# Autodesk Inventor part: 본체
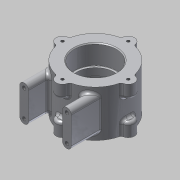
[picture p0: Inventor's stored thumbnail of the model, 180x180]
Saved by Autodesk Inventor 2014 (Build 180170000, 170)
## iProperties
Created: 2015-03
Part Number: 본체
Material: 알루미늄 6061
Document SubType Name: Modeling
Designer: MYHOME
Mass: 450.776 g
Surface Area: 332.745 cm^2
Volume: 166.338 cm^3
Density: 2.71 g/cm^3
Appearance: 알루미늄 - 평지
Author: MYHOME
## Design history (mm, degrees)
sketch "스케치1"
  geometry: C1 r 37 at (0, 0); 1 further point
  constraints: 1 centre point, 1 coincident
  dimensions: "d0" = 74 diameter of C1
extrude "돌출1" new body sketch "스케치1" stored distance "d1" = 52; taper "d2" = 0 deg
sketch "스케치2"
  geometry: C1 r 7 at (0, 37); 1 further point
  constraints: 2 vertical alignment, 1 centre point, 1 other
  dimensions: "d3" = 7 radius of C1
extrude "돌출2" join sketch "스케치2" distance "d4" = 15; taper "d5" = 0 deg
hole "구멍1" diameter "d11" = 42; stored, may be unused: countersink angle "d15" = 90 deg, drill point angle "d17" = 0 deg; dims "d9" = 10, "d10" = 10, "d12" = 6, "d13" = 47, "d14" = 22, "d16" = 26
sketch "스케치3"
  geometry: L1 (-29, -22.978)-(-19, -22.978); L2 (-19, -22.978)-(-19, -56); L3 (-19, -56)-(-29, -56); L4 (-29, -56)-(-29, -22.978); L5 (-29, -22.978)-(-19, -56); L6 (-19, -22.978)-(-29, -56); L7 (19, -22.978)-(29, -22.978); L8 (29, -22.978)-(29, -56); L9 (29, -56)-(19, -56); L10 (19, -56)-(19, -22.978); L11 (19, -22.978)-(29, -56); L12 (29, -22.978)-(19, -56); A1 r 37 centre (0, 0) between (-36.338, -6.969) and (-6.969, -36.338) reference; A2 r 37 centre (0, 0) between (6.969, -36.338) and (36.338, -6.969) reference; 3 further points
  constraints: 24 end point, 4 midpoint, 4 parallel, 2 horizontal, 2 perpendicular, 2 point on circle, 1 collinear
  dimensions: "d18" = 48 distance of point (24, -39.489) point (-24, -39.489); "d19" = 24 horizontal distance of point (-24, -39.489) point (0, 0); "d20" = 56 distance from line of L3 point (0, 0); "d21" = 10 distance of L1.start L1.end; "d22" = 10 distance of L7.start L7.end
extrude "돌출3" join sketch "스케치3" stored distance "d23" = 40; taper "d24" = 0 deg
sketch "스케치4"
  geometry: A1 r 7 centre (0, 37) between (6.969, 36.338) and (-6.969, 36.338) reference; A2 r 7 centre (-37, 0) between (-36.338, 6.969) and (-36.338, -6.969) reference; A3 r 7 centre (0, -37) between (-6.969, -36.338) and (6.969, -36.338) reference; A4 r 7 centre (37, 0) between (36.338, -6.969) and (36.338, 6.969) reference; 4 further points
  constraints: 4 coincident
hole "구멍2" sketch "스케치4" at (0, 37), (-37, 0), (0, -37), (37, 0) diameter "d25" = 3.242; stored, may be unused: countersink angle "d29" = 90 deg, drill point angle "d31" = 118 deg; dims "d26" = 8, "d27" = 47, "d28" = 22, "d30" = 11
chamfer "모따기1" distance "d32" = 1; stored, may be unused: second distance "d33" = 2, angle "d34" = 45 deg
fillet "모깎기1" dims "d35" = 3
fillet "모깎기2" dims "d36" = 0.3
fillet "모깎기3" dims "d37" = 5
fillet "모깎기4" dims "d38" = 3
fillet "모깎기5" dims "d39" = 3
sketch "스케치5"
  geometry: L1 (43, 30)-(43, 0) reference; L2 (53, 30)-(53, 0) reference; A1 r 5 centre (0, 0) between (-5, 0) and (5, 0) reference; A2 r 5 centre (0, 30) between (5, 30) and (-5, 30) reference; A3 r 5 centre (48, 30) between (53, 30) and (43, 30) reference; A4 r 5 centre (48, 0) between (43, 0) and (53, 0) reference; 5 further points
  constraints: 4 coincident
hole "구멍3" sketch "스케치5" at (0, 30), (0, 0), (48, 0), (48, 30) diameter "d40" = 4.134; stored, may be unused: countersink angle "d44" = 90 deg, drill point angle "d46" = 118 deg; dims "d41" = 6, "d42" = 47, "d43" = 22, "d45" = 8
sketch "스케치6"
  geometry: L1 (0, 0)-(-44, 0); L2 (0, 0)-(-26.163, 26.163); A1 r 37 centre (0, 0) between (-9.104, 35.863) and (-35.863, 9.104) reference; A2 r 7 centre (-37, 0) between (-38.239, 6.889) and (-38.239, -6.889) reference; 2 further points
  constraints: 4 end point, 2 point on circle, 1 coincident
  dimensions: "d47" = 45 deg angle of L1 L2
node "작업 평면4"
sketch "스케치9"
  geometry: 2 further points
  constraints: 1 coincident, 1 other
feature "엠보싱2" sketch "스케치9" dims "d53" = 0.5, "d54" = 0
node "솔리드1"
pattern_circular "원형 패턴1" dims angle "d7" = 360 deg
mirror "대칭1"
mirror "대칭2"
mirror "대칭3"
node "투영된 루프1"
